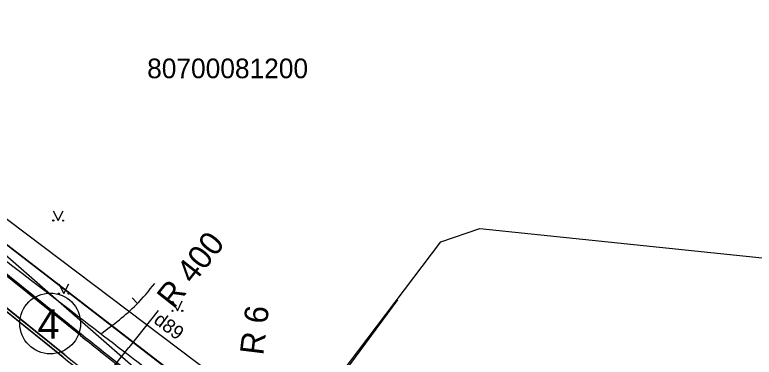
# Model space of a CAD drawing. Extents: x 514086 to 514457, y 297399 to 297567.
# Drawn here: x 514181.92 to 514219.51, y 297463.61 to 297481.03 of the extents above; entities that cross this region are included whole.
import ezdxf

# ---------------------------------------------------------------- set-up
doc = ezdxf.new("R2010")
doc.units = 0
for name, color, linetype in [('AA_Apzimejumi', 7, 'Continuous'), ('AA_Brauktuve', 7, 'Continuous'), ('AA_cela_mala', 7, 'Continuous'), ('AA_Ietve', 7, 'Continuous'), ('AA_izmeri', 7, 'Continuous'), ('AA_Zale', 7, 'Continuous'), ('Level 21', 7, 'Continuous'), ('Level 23', 7, 'Continuous'), ('Level 29', 7, 'Continuous'), ('Level 32', 7, 'Continuous'), ('Level 37', 7, 'Continuous'), ('Level 46', 7, 'Continuous'), ('Level 59', 7, 'Continuous'), ('Level 8', 7, 'Continuous')]:
    doc.layers.add(name, color=color, linetype=linetype)

msp = doc.modelspace()

# ---------------------------------------------------------------- linework, layer by layer
at = {"layer": 'AA_Apzimejumi'}
msp.add_circle((514183.716, 297465.326), 1.546, dxfattribs=at)
at = {"layer": 'AA_Brauktuve'}
msp.add_lwpolyline([(514184.371, 297463.607), (514146.894, 297493.805)], dxfattribs=at)
msp.add_arc((514308.288, 297617.396), 197.5, 231.13942, 232.4775, dxfattribs=at)
at = {"layer": 'AA_cela_mala'}
for p, q in [((514147.835, 297494.973), (514185.313, 297464.775)), ((514185.262, 297464.713), (514147.785, 297494.911)), ((514184.466, 297463.724), (514146.988, 297493.922)), ((514146.894, 297493.805), (514184.371, 297463.607))]:
    msp.add_line(p, q, dxfattribs=at)
for radius in [196.08, 196, 197.5, 197.35]:
    msp.add_arc((514308.288, 297617.396), radius, 231.13942, 232.4775, dxfattribs=at)
at = {"layer": 'AA_Ietve'}
for points in [[(514185.262, 297464.713), (514147.791, 297494.906)], [(514146.982, 297493.927), (514184.466, 297463.724)]]:
    msp.add_lwpolyline(points, dxfattribs=at)
for radius in [196.08, 197.35]:
    msp.add_arc((514308.288, 297617.396), radius, 231.13942, 232.4775, dxfattribs=at)
at = {"layer": 'AA_izmeri'}
for p in [(514189.203, 297465.987), (514184.63, 297460.206)]:
    msp.add_line(p, (514187.714, 297464.105), dxfattribs=at)
at = {"layer": 'AA_Zale'}
msp.add_line((514175.859, 297473.677), (514193.845, 297459.804), dxfattribs=at)
for points in [[(514197.26, 297461.293), (514196.873, 297461.611), (514193.845, 297459.804), (514175.859, 297473.677), (514146.591, 297497.26)], [(514147.835, 297494.973), (514185.313, 297464.775)]]:
    msp.add_lwpolyline(points, dxfattribs=at)
msp.add_arc((514308.288, 297617.396), 196, 231.13942, 232.4775, dxfattribs=at)
at = {"layer": 'Level 21'}
msp.add_spline([(514167.656, 297460.196), (514167.656, 297463.017), (514169.677, 297465.792), (514173.482, 297465.792), (514178.65, 297462.077), (514185.698, 297456.857), (514187.671, 297455.211), (514188.469, 297452.531), (514186.966, 297450.274), (514184.429, 297447.265)], degree=3, dxfattribs=at)
at = {"layer": 'Level 23'}
for p, q in [((514183.875, 297471.062), (514184.125, 297470.562)), ((514184.125, 297470.562), (514184.375, 297471.062)), ((514184.156, 297467.343), (514184.406, 297466.843)), ((514184.406, 297466.843), (514184.656, 297467.343)), ((514189.934, 297466.468), (514190.184, 297465.968)), ((514190.184, 297465.968), (514190.434, 297466.468))]:
    msp.add_line(p, q, dxfattribs=at)
for centre, radius in [((514183.874, 297470.562), 0.028), ((514184.374, 297470.562), 0.0263), ((514184.155, 297466.843), 0.028), ((514184.655, 297466.843), 0.0263), ((514189.934, 297465.968), 0.028), ((514190.434, 297465.968), 0.0263)]:
    msp.add_circle(centre, radius, dxfattribs=at)
at = {"layer": 'Level 29'}
for p, q in [((514203.568, 297469.479), (514205.558, 297470.155)), ((514205.558, 297470.155), (514224.892, 297468.141)), ((514194.45, 297457.413), (514203.568, 297469.479))]:
    msp.add_line(p, q, dxfattribs=at)
at = {"layer": 'Level 32'}
msp.add_line((514188.153, 297466.338), (514187.878, 297466.629), dxfattribs=at)
msp.add_spline([(514186.303, 297464.804), (514188.098, 297466.284), (514189.028, 297467.354)], degree=3, dxfattribs=at)
at = {"layer": 'Level 37'}
msp.add_lwpolyline([(514201.367, 297466.523), (514197.303, 297461.007), (514196.259, 297459.707)], dxfattribs=at)
for points in [[(514139.874, 297497.035), (514148.452, 297493.087), (514152.9, 297490.654), (514155.012, 297489.24), (514157.055, 297487.727), (514160.163, 297485.252), (514163.225, 297482.729), (514166.288, 297480.21), (514169.399, 297477.75), (514184.679, 297466.049), (514188.685, 297462.979), (514190.692, 297461.445), (514192.708, 297459.912), (514193.134, 297459.688), (514193.613, 297459.574), (514194.114, 297459.524), (514194.606, 297459.489), (514195.045, 297459.442), (514195.506, 297459.417), (514195.979, 297459.548), (514196.259, 297459.707)], [(514136.849, 297494.086), (514140.775, 297492.444), (514142.699, 297491.153), (514143.967, 297490.173), (514145.225, 297489.179), (514146.485, 297488.19), (514147.764, 297487.226), (514149.635, 297485.885), (514151.52, 297484.563), (514153.402, 297483.236), (514155.263, 297481.88), (514159.161, 297478.934), (514163.043, 297475.965), (514166.923, 297472.996), (514170.82, 297470.048), (514173.26, 297468.237), (514175.709, 297466.438), (514178.159, 297464.639), (514180.6, 297462.828), (514184.429, 297459.874), (514186.323, 297458.371), (514188.215, 297456.863), (514189.034, 297456.154), (514191.11, 297453.709)]]:
    msp.add_spline(points, degree=3, dxfattribs=at)
at = {"layer": 'Level 46'}
msp.add_lwpolyline([(514139.134, 297486.37), (514229.261, 297420.493), (514237.863, 297414.208), (514250.009, 297428.181), (514295.433, 297494.723), (514312.775, 297524.542), (514316.491, 297528.738), (514320.446, 297531.016), (514328.236, 297532.215), (514332.539, 297530.572), (514332.631, 297530.536), (514341.642, 297542.18), (514320.211, 297553.997), (514285.885, 297496.27), (514243.195, 297433.696), (514241.534, 297432.407), (514239.451, 297432.203), (514209.969, 297445.237), (514194.45, 297457.413), (514175.859, 297473.677), (514139.316, 297503.122), (514133.046, 297508.174), (514130.604, 297489.221)], close=True, dxfattribs=at)
at = {"layer": 'Level 8'}
msp.add_lwpolyline([(514200.623, 297456.189), (514178.139, 297473.151), (514155.647, 297490.079), (514143.111, 297496.557), (514135.656, 297500), (514119.377, 297505.512), (514108.036, 297513.213), (514096.037, 297522.278)], dxfattribs=at)

# ---------------------------------------------------------------- texts
at = {"layer": 'AA_Apzimejumi'}
msp.add_text('4', height=1.5, dxfattribs=at).set_placement((514183.076, 297464.55))
at = {"layer": 'AA_izmeri'}
for s, rotation, p in [('R 400', 51.6522, (514189.986, 297466.021)), ('R 6', 83.0032, (514194.544, 297463.676))]:
    msp.add_text(s, height=1.2, rotation=rotation, dxfattribs=at).set_placement(p)
at = {"layer": 'Level 59'}
msp.add_text('80700081200', height=1, dxfattribs=at).set_placement((514188.646, 297477.803))
at = {"layer": 'Level 8'}
msp.add_text('d89', height=0.7, rotation=322.9682, dxfattribs=at).set_placement((514188.929, 297465.387))

doc.saveas('drawing.dxf')
